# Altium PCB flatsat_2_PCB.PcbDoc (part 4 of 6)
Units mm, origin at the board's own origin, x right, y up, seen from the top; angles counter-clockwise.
Board outline 400 x 250 mm, 4 copper layers (Top Layer, FlatSat GND, FlatSat VCC, Bottom Layer), stack 2.102 mm thick; 196 components, 289 nets, 1724 pads, 1139 vias.
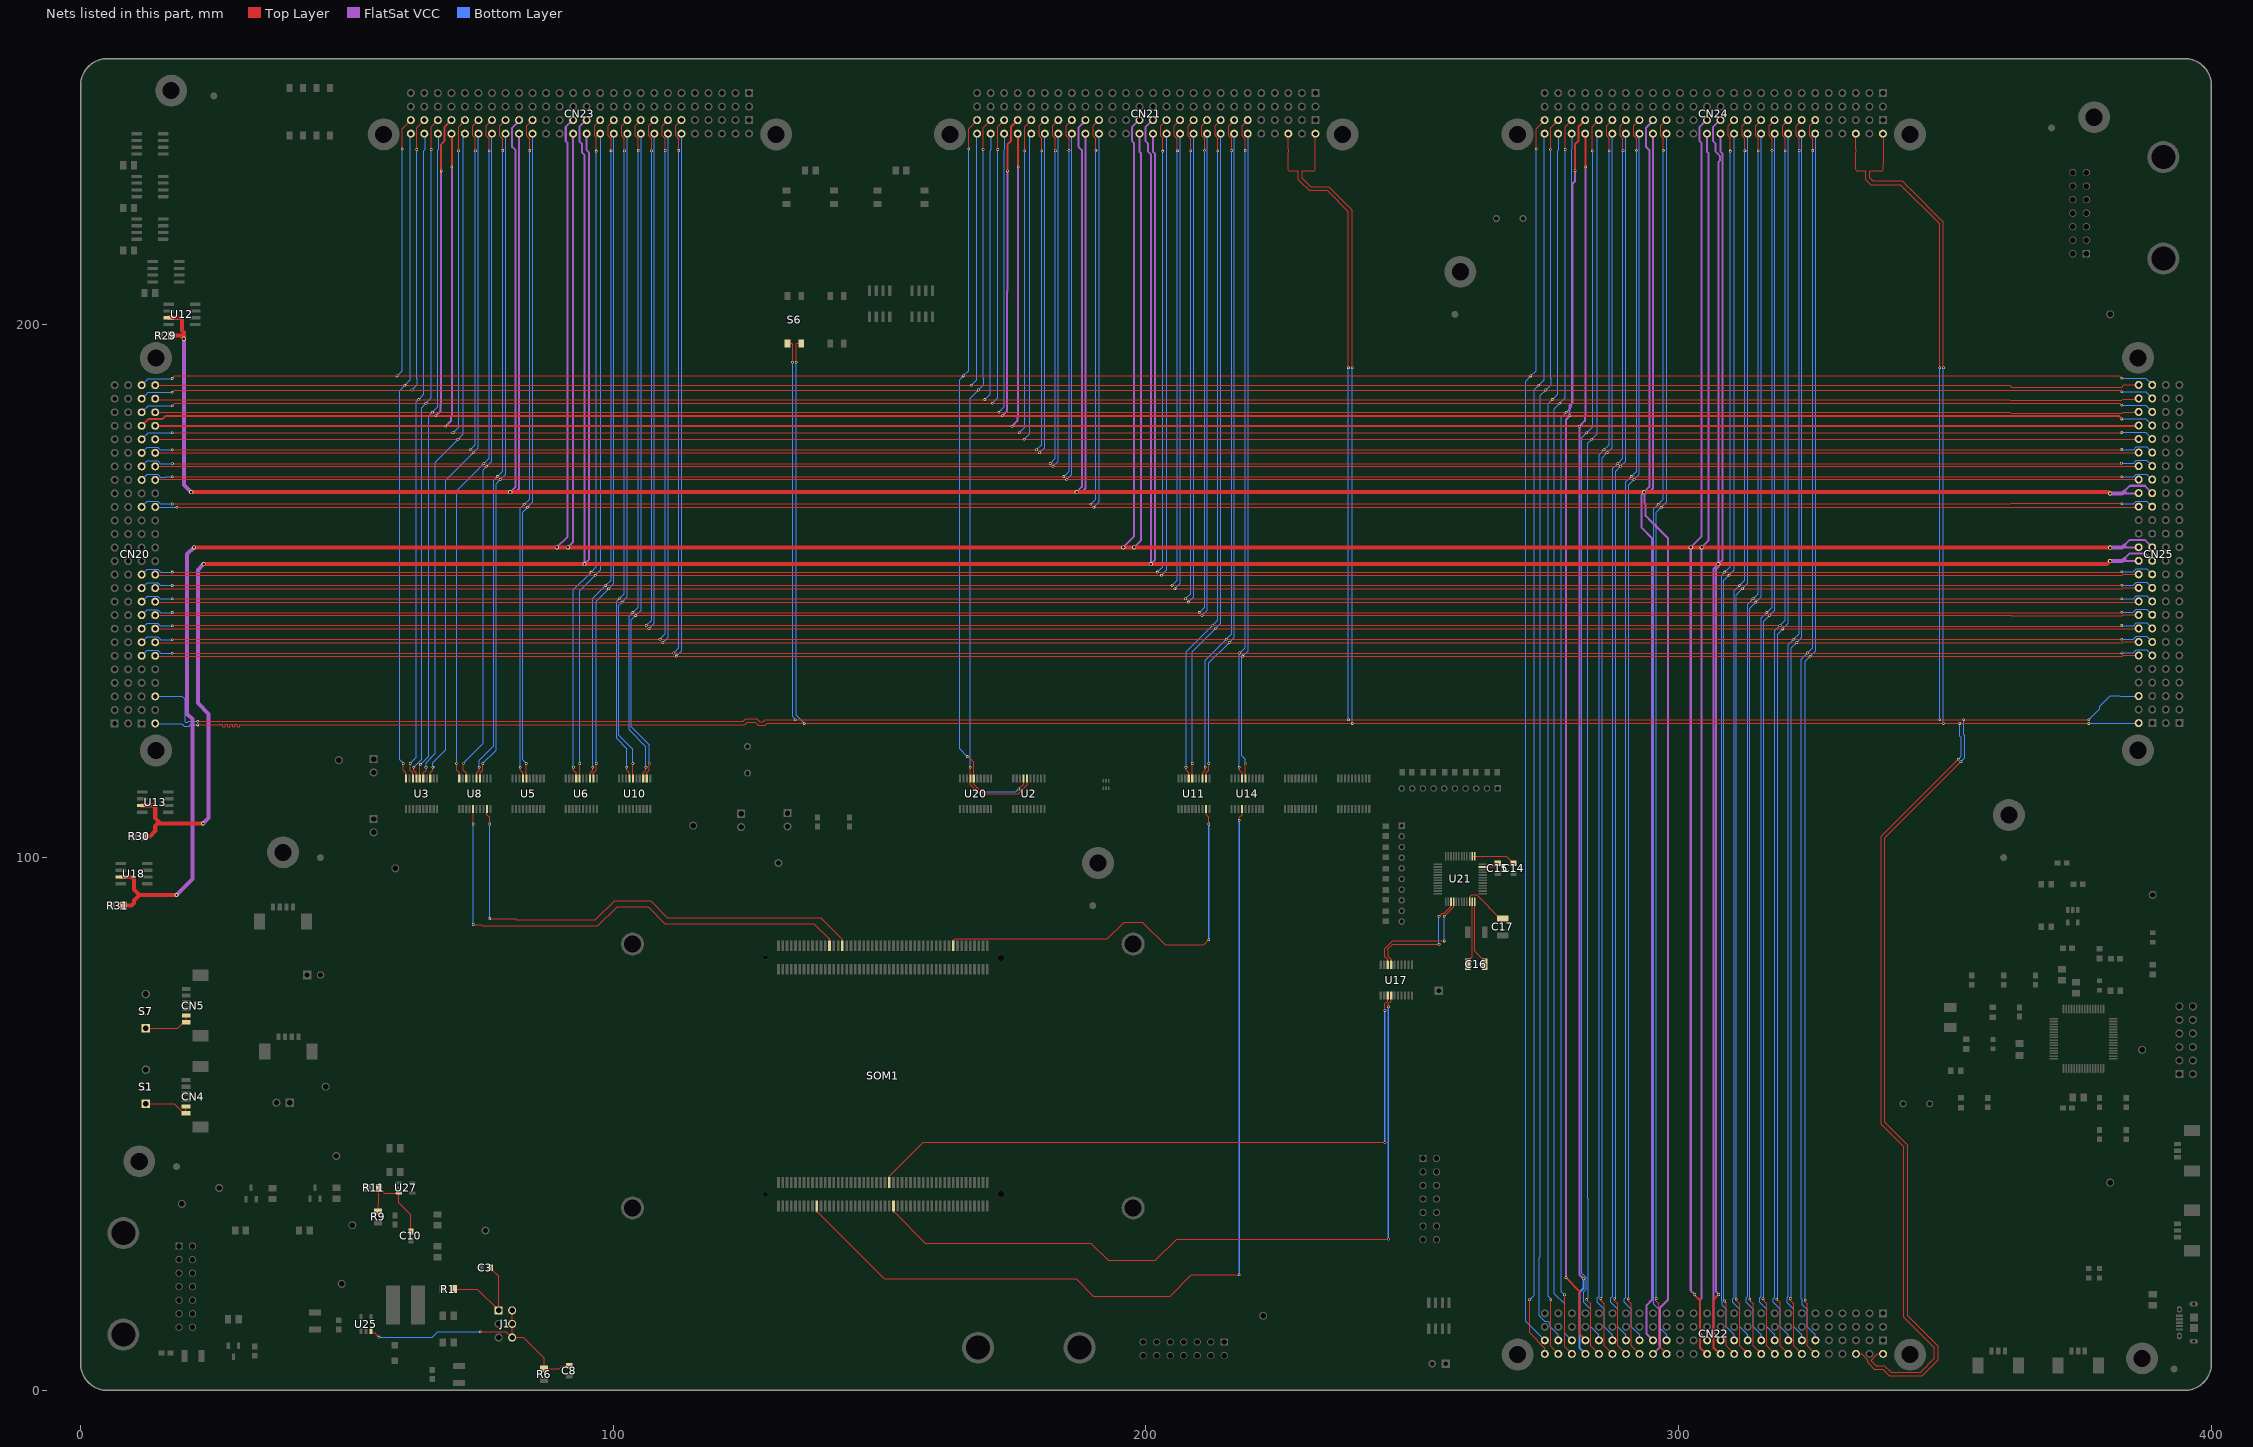
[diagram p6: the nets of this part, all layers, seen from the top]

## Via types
v1: diameter 0.508, hole 0.3, Top Layer to Bottom Layer, tented both sides, 1073 vias
v2: diameter 0.762, hole 0.45, Top Layer to Bottom Layer, tented both sides, 66 vias

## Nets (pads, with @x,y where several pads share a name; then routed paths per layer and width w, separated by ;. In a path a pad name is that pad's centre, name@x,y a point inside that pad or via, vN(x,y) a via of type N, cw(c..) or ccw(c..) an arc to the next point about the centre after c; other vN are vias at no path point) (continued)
H2-11: CN20.63 CN21.63 CN22.63 CN23.63 CN24.63 CN25.63 U14.17 | length 836.7
  Top Layer w0.203: v1(17.173,138.375) 17.215,138.418 v1(111.305,138.418) v1(217.625,138.418) v1(324.165,138.418) 324.211,138.371 382.95,138.371 382.955,138.376 383.163,138.376 v1(383.221,138.435) ; v1@112.306,232.749 112.306,234.909 111.73,235.485 111.73,237.415 CN23.63@112.78,238.465 ; v1(217.518,116.994) 217.518,116.421 218.025,115.913 U14.17@218.025,114.87 ; v1@218.626,232.749 218.626,234.909 218.05,235.485 218.05,237.415 CN21.63@219.1,238.465 ; v1@325.166,232.749 325.166,234.909 324.59,235.485 324.59,237.415 CN24.63@325.64,238.465
  Bottom Layer w0.203: CN20.63@11.455,137.9 12.505,138.95 14.435,138.95 15.011,138.374 17.171,138.374 v1(17.173,138.375) ; v1(111.305,138.418) 112.305,139.418 v1(112.305,232.747) v1@112.306,232.749 ; v1(217.518,116.994) 217.518,138.228 217.625,138.335 v1(217.625,138.418) 218.625,139.418 v1(218.625,232.747) ; v1(325.165,232.747) 325.165,139.418 v1(324.165,138.418) 323,137.253 323,17.193 323.243,16.95 323.243,16.111 324.158,15.196 324.158,11.978 325.668,10.467 CN22.63@325.668,9.388 ; v1(383.221,138.435) 385.36,138.435 385.93,139.005 387.86,139.005 CN25.63@388.91,137.955
H2-12: CN20.64 CN21.64 CN22.64 CN23.64 CN24.64 CN25.64 U14.16 | length 823.3
  Top Layer w0.203: CN20.64@14,137.9 14.058,137.842 v1(111.838,137.842) v1(218.158,137.842) 218.16,137.84 324.696,137.84 v1(324.698,137.838) ; U14.16@218.675,114.87 v1(218.675,117.679) ; v1(323.777,16.895) 323.718,16.837 323.718,16.669 323.708,16.658 324.158,16.208 324.158,8.354 CN22.64@325.668,6.843 ; v1@324.698,137.842 383.359,137.842 383.479,137.962 386.358,137.962 CN25.64@386.365,137.955
  Bottom Layer w0.203: v1(111.838,137.842) 112.838,138.842 CN23.64@112.838,235.862 ; v1(218.675,117.679) 218.675,118.446 218,119.121 218,137.601 218.158,137.759 v1(218.158,137.842) 219.158,138.842 CN21.64@219.158,235.862 ; v1(323.777,16.895) 323.722,16.95 323.722,136.865 324.694,137.838 v1(324.698,137.838) ; v1@324.698,137.842 325.698,138.842 CN24.64@325.698,235.862
H2-13: CN20.65 CN21.65 CN22.65 CN23.65 CN24.65 CN25.65 U11.13 | length 835.7
  Top Layer w0.203: v1(17.166,140.925) 17.225,140.983 17.421,140.983 17.438,141 v1(108.755,141) v1(215.075,141) v1(321.615,141) 383.178,141 v1(383.199,140.979) v1@383.179,140.96 ; v1(109.755,232.754) 109.755,234.92 109.19,235.485 109.19,237.41 CN23.65@110.24,238.46 ; U11.13@210.625,114.87 210.625,115.913 211.132,116.421 v1(211.132,116.994) ; v1(216.075,232.754) 216.075,234.92 215.51,235.485 215.51,237.41 CN21.65@216.56,238.46 ; v1(322.615,232.754) 322.615,234.92 322.05,235.485 322.05,237.41 CN24.65@323.1,238.46
  Bottom Layer w0.203: CN20.65@11.46,140.44 12.51,141.49 14.435,141.49 15,140.925 v1(17.166,140.925) ; v1(108.755,141) 109.755,142 v1(109.755,232.754) ; v1(211.132,116.994) 211.132,137.057 v1(215.075,141) 216.075,142 v1(216.075,232.754) ; v1(322.615,232.754) 322.615,142 v1(321.615,141) 320.615,140 320.615,36 320.615,17.648 320.381,17.414 320.381,16.433 321.618,15.196 321.618,11.978 323.128,10.467 CN22.65@323.128,9.383 ; v1(383.199,140.979) 385.365,140.979 385.93,141.545 387.855,141.545 CN25.65@388.905,140.495
H2-14: CN20.66 CN21.66 CN22.66 CN23.66 CN24.66 CN25.66 U11.12 | length 822.4
  Top Layer w0.203: CN20.66@14,140.44 14.049,140.391 v1(109.289,140.391) v1(215.609,140.391) v1(322.149,140.391) 383.365,140.391 383.489,140.515 386.345,140.515 CN25.66@386.365,140.495 ; U11.12@211.275,114.87 211.275,115.913 211.782,116.421 v1(211.782,117.679) ; v1(320.957,17.235) 320.957,16.869 321.618,16.208 321.618,8.354 CN22.66@323.128,6.843
  Bottom Layer w0.203: v1(109.289,140.391) 110.289,141.391 CN23.66@110.289,235.871 ; v1(211.782,117.679) 211.782,136.564 v1(215.609,140.391) 216.609,141.391 CN21.66@216.609,235.871 ; v1(320.957,17.235) 320.957,17.312 321.151,17.507 321.151,139.393 v1(322.149,140.391) 323.149,141.391 CN24.66@323.149,235.871
H2-15: CN20.67 CN21.67 CN22.67 CN23.67 CN24.67 CN25.67 U11.17 | length 833.5
  Top Layer w0.203: v1(17.185,143.514) 17.244,143.572 17.442,143.572 17.457,143.587 v1(106.166,143.587) v1(212.486,143.587) v1(319.026,143.587) 319.109,143.587 319.215,143.481 382.908,143.481 382.938,143.51 383.122,143.51 v1(383.18,143.569) ; v1(107.166,232.735) 107.166,234.969 106.65,235.485 106.65,237.41 CN23.67@107.7,238.46 ; v1(207.518,116.994) 207.518,116.421 208.025,115.913 U11.17@208.025,114.87 ; v1(213.486,232.735) 213.486,234.969 212.97,235.485 212.97,237.41 CN21.67@214.02,238.46 ; v1(320.026,232.735) 320.026,234.969 319.51,235.485 319.51,237.41 CN24.67@320.56,238.46
  Bottom Layer w0.203: CN20.67@11.46,142.98 12.51,144.03 14.435,144.03 14.951,143.514 v1(17.185,143.514) ; v1(106.166,143.587) 107.166,144.587 v1(107.166,232.735) ; v1(207.518,116.994) 207.518,138.618 v1(212.486,143.587) 213.486,144.587 v1(213.486,232.735) ; v1(320.026,232.735) 320.026,144.587 v1(319.026,143.587) 318.038,142.598 318.038,17.481 317.767,17.21 317.767,16.508 319.078,15.196 319.078,11.978 320.588,10.467 CN22.67@320.588,9.383 ; v1(383.18,143.569) 385.414,143.569 385.93,144.085 387.855,144.085 CN25.67@388.905,143.035
H2-16: CN20.68 CN21.68 CN22.68 CN23.68 CN24.68 CN25.68 U11.16 | length 819.9
  Top Layer w0.203: CN20.68@14,142.98 v1(106.7,142.98) v1(213.02,142.98) 213.036,142.964 319.544,142.964 v1(319.56,142.947) ; U11.16@208.675,114.87 v1(208.675,117.679) ; v1(318.437,17.126) 319.078,16.485 319.078,8.354 CN22.68@320.588,6.843 ; v1@319.56,142.98 386.31,142.98 CN25.68@386.365,143.035
  Bottom Layer w0.203: v1(106.7,142.98) 107.7,143.98 CN23.68@107.7,235.92 ; v1(208.675,117.679) 208.675,138.635 v1(213.02,142.98) 214.02,143.98 CN21.68@214.02,235.92 ; v1(318.437,17.126) 318.437,17.255 318.56,17.378 318.56,36 318.56,141.98 319.527,142.947 v1(319.56,142.947) ; v1@319.56,142.98 320.56,143.98 CN24.68@320.56,235.92
H2-17: CN20.69 CN21.69 CN22.69 CN23.69 CN24.69 CN25.69 U10.13 | length 830.6
  Top Layer w0.203: v1(17.179,146.014) v1(103.666,146.014) v1(209.986,146.014) v1(316.526,146.014) 383.131,146.014 v1(383.186,146.069) ; v1(104.666,232.741) 104.666,234.929 104.11,235.485 104.11,237.435 CN23.69@105.135,238.46 ; U10.13@105.625,114.87 105.625,115.913 106.132,116.421 v1(106.132,116.994) ; v1(210.986,232.741) 210.986,234.929 210.43,235.485 210.43,237.435 CN21.69@211.455,238.46 ; v1(317.526,232.741) 317.526,234.929 316.97,235.485 316.97,237.435 CN24.69@317.995,238.46
  Bottom Layer w0.203: CN20.69@11.46,145.545 12.485,146.57 14.435,146.57 14.991,146.014 v1(17.179,146.014) ; v1(104.666,232.741) 104.666,147.014 v1(103.666,146.014) 103,145.348 103,124 106.132,120.868 v1(106.132,116.994) ; v1(209.986,146.014) 210.986,147.014 v1(210.986,232.741) ; v1(317.526,232.741) 317.526,147.014 v1(316.526,146.014) 315.526,145.014 315.526,36 315.526,17.639 315.227,17.339 315.227,16.508 316.538,15.196 316.538,11.978 318.048,10.467 CN22.69@318.048,9.383 ; v1(383.186,146.069) 385.374,146.069 385.93,146.625 387.88,146.625 CN25.69@388.905,145.6
H2-18: CN20.70 CN21.70 CN22.70 CN23.70 CN24.70 CN25.70 U10.12 | length 817.9
  Top Layer w0.203: CN20.70@14,145.52 14.04,145.48 v1(104.2,145.48) v1(210.52,145.48) v1(317.06,145.48) 362.403,145.48 362.456,145.428 383.3,145.428 383.473,145.602 386.339,145.602 CN25.70@386.365,145.575 ; CN23.70@105.16,235.92 CN23.70@105.2,235.88 ; U10.12@106.275,114.87 106.275,115.913 106.782,116.421 v1(106.782,117.679) ; CN21.70@211.48,235.92 CN21.70@211.52,235.88 ; v1(315.834,17.192) 315.877,17.149 315.877,16.869 316.538,16.208 316.538,8.354 CN22.70@318.048,6.843 ; CN24.70@318.02,235.92 CN24.70@318.06,235.88
  Bottom Layer w0.203: CN23.70@105.16,235.92 105.2,235.88 105.2,146.48 v1(104.2,145.48) 103.381,144.662 103.381,124.619 106.782,121.218 v1(106.782,117.679) ; v1(210.52,145.48) 211.52,146.48 211.52,235.88 CN21.70@211.48,235.92 ; v1(315.834,17.192) 315.893,17.251 315.893,17.466 315.972,17.546 315.972,144.393 v1(317.06,145.48) 318.06,146.48 318.06,235.88 CN24.70@318.02,235.92
H2-19: CN20.71 CN21.71 CN22.71 CN23.71 CN24.71 CN25.71 U10.17 | length 827.4
  Top Layer w0.203: v1(17.183,148.585) 17.188,148.58 18.699,148.58 18.704,148.585 v1(101.095,148.585) v1(207.415,148.585) v1(313.955,148.585) 383.135,148.585 v1(383.182,148.632) ; v1@102.1,232.732 v1(102.095,232.737) 102.095,234.96 101.57,235.485 101.57,237.41 CN23.71@102.62,238.46 ; v1(102.518,116.994) 102.518,116.421 103.025,115.913 U10.17@103.025,114.87 ; v1@208.42,232.732 v1(208.415,232.737) 208.415,234.96 207.89,235.485 207.89,237.41 CN21.71@208.94,238.46 ; v1@314.96,232.732 v1(314.955,232.737) 314.955,234.96 314.43,235.485 314.43,237.41 CN24.71@315.48,238.46
  Bottom Layer w0.203: CN20.71@11.46,148.06 12.51,149.11 14.435,149.11 14.96,148.585 v1(17.183,148.585) ; v1(102.095,232.737) 102.095,149.585 v1(101.095,148.585) 100.605,148.094 100.605,122.395 102.518,120.482 v1(102.518,116.994) ; v1(207.415,148.585) 208.415,149.585 v1(208.415,232.737) ; v1(314.955,232.737) 314.955,149.585 v1(313.955,148.585) 312.98,147.609 312.98,17.656 312.687,17.363 312.687,16.508 313.998,15.196 313.998,11.978 315.508,10.467 CN22.71@315.508,9.383 ; v1(383.182,148.632) 383.19,148.64 385.405,148.64 385.93,149.165 387.855,149.165 CN25.71@388.905,148.115
H2-20: CN20.72 CN21.72 CN22.72 CN23.72 CN24.72 CN25.72 U10.16 | length 814.5
  Top Layer w0.203: CN20.72@14,148.06 14.078,147.982 v1(101.629,147.982) v1(207.949,147.982) v1(314.489,147.982) 386.232,147.982 CN25.72@386.365,148.115 ; U10.16@103.675,114.87 v1(103.675,117.679) ; v1(313.342,17.11) 313.337,17.106 313.337,16.869 313.998,16.208 313.998,8.354 CN22.72@315.508,6.843
  Bottom Layer w0.203: CN23.72@102.629,235.911 102.629,148.982 v1(101.629,147.982) 101,147.353 101,123 103.675,120.325 v1(103.675,117.679) ; v1(207.949,147.982) 208.949,148.982 CN21.72@208.949,235.911 ; v1(313.342,17.11) 313.361,17.129 313.361,146.854 v1(314.489,147.982) 315.489,148.982 CN24.72@315.489,235.911
H2-21: CN20.73 CN21.73 CN22.73 CN23.73 CN24.73 CN25.73 U6.13 | length 825
  Top Layer w0.203: v1(17.187,151.105) v1(98.575,151.105) v1(204.895,151.105) v1(311.435,151.105) 383.123,151.105 v1(383.178,151.16) ; U6.13@95.625,114.87 95.625,115.913 96.132,116.421 v1(96.132,116.994) ; v1(99.575,232.733) 99.575,234.94 99.03,235.485 99.03,237.41 CN23.73@100.08,238.46 ; v1(205.895,232.733) 205.895,234.94 205.35,235.485 205.35,237.41 CN21.73@206.4,238.46 ; v1(312.435,232.733) 312.435,234.94 311.89,235.485 311.89,237.41 CN24.73@312.94,238.46
  Bottom Layer w0.203: CN20.73@11.46,150.6 12.51,151.65 14.435,151.65 14.98,151.105 v1(17.187,151.105) ; v1(96.132,116.994) 96.132,148.663 v1(98.575,151.105) 99.575,152.105 v1(99.575,232.733) ; v1(204.895,151.105) 205.895,152.105 v1(205.895,232.733) ; v1(312.435,232.733) 312.435,152.105 v1(311.435,151.105) 310.452,150.123 310.452,17.515 310.147,17.21 310.147,16.508 311.458,15.196 311.458,11.978 312.968,10.467 CN22.73@312.968,9.383 ; v1(383.178,151.16) 385.386,151.16 385.93,151.705 387.855,151.705 CN25.73@388.905,150.655
H2-22: CN20.74 CN21.74 CN22.74 CN23.74 CN24.74 CN25.74 U6.12 | length 811.8
  Top Layer w0.203: CN20.74@14,150.6 14.123,150.477 v1(99.108,150.477) v1(205.428,150.477) v1(311.968,150.477) 383.249,150.477 383.479,150.706 386.314,150.706 CN25.74@386.365,150.655 ; U6.12@96.275,114.87 96.275,115.913 96.782,116.421 v1(96.782,117.679) ; v1@310.797,17.106 310.797,16.869 311.458,16.208 311.458,8.354 CN22.74@312.968,6.843
  Bottom Layer w0.203: v1(96.782,117.679) 96.782,148.151 v1(99.108,150.477) 100.108,151.477 CN23.74@100.108,235.892 ; v1(205.428,150.477) 206.428,151.477 CN21.74@206.428,235.892 ; v1(310.798,17.106) 310.833,17.141 310.833,149.342 v1(311.968,150.477) 312.968,151.477 CN24.74@312.968,235.892
H2-23: CN20.75 CN21.75 CN22.75 CN23.75 CN24.75 CN25.75 U6.17 | length 822
  Top Layer w0.203: v1(17.183,153.612) v1(95.818,153.612) v1(202.138,153.612) v1(308.678,153.612) 383.128,153.612 v1(383.183,153.667) ; v1(92.518,116.994) 92.518,116.421 93.025,115.913 U6.17@93.025,114.87 ; v1(96.818,232.653) 96.818,235.157 96.49,235.485 96.49,237.41 CN23.75@97.54,238.46 ; v1(203.138,232.653) 203.138,235.157 202.81,235.485 202.81,237.41 CN21.75@203.86,238.46 ; v1(309.678,232.653) 309.678,235.157 309.35,235.485 309.35,237.41 CN24.75@310.4,238.46
  Bottom Layer w0.203: CN20.75@11.46,153.14 12.51,154.19 14.435,154.19 15.013,153.612 v1(17.183,153.612) ; v1(92.518,116.994) 92.518,150.312 v1(95.818,153.612) 96.818,154.612 v1(96.818,232.653) ; v1(202.138,153.612) 203.138,154.612 v1(203.138,232.653) ; v1(309.678,232.653) 309.678,154.612 308.126,153.061 308.126,16.859 308.136,16.849 308.136,15.978 308.918,15.196 308.918,11.978 310.428,10.467 CN22.75@310.428,9.383 ; v1(383.183,153.667) 385.352,153.667 385.93,154.245 387.855,154.245 CN25.75@388.905,153.195
H2-24: CN20.76 CN21.76 CN22.76 CN23.76 CN24.76 CN25.76 U6.16 | length 809.3
  Top Layer w0.203: CN20.76@14,153.14 14.122,153.018 v1(96.601,153.018) v1(202.921,153.018) v1(309.461,153.018) 383.288,153.018 383.502,153.231 386.329,153.231 CN25.76@386.365,153.195 ; U6.16@93.675,114.87 v1(93.675,117.679) ; v1(308.67,16.772) 308.67,16.69 308.918,16.442 308.918,8.354 CN22.76@310.428,6.843
  Bottom Layer w0.203: v1(93.675,117.679) 93.675,150.092 v1(96.601,153.018) 97.601,154.018 97.601,235.859 CN23.76@97.54,235.92 ; v1(202.921,153.018) 203.921,154.018 203.921,235.859 CN21.76@203.86,235.92 ; v1(308.67,16.772) 308.67,16.855 308.508,17.017 308.508,152.064 310.461,154.018 310.461,235.859 CN24.76@310.4,235.92
H2-25: CN21.77 CN21.78 CN22.77 CN22.78 CN23.77 CN23.78 CN24.77 CN24.78 CN25.77 CN25.78 R30.2 U13.7 | length 1232.5
  Top Layer w0.381: v1(307.54,18) 306.54,17 306.54,8 CN22.78@307.697,6.843
  Top Layer w0.762: U13.7@11.53,109.788 13.554,109.788 14,109.342 14,107.423 15,106.423 ; R30.2@12.016,104 13,104 14,105 14,105.977 14.446,106.423 15,106.423 ; v2(23,106.423) 15,106.423 ; v2(23.099,155.099) v2(94.582,155.099) v2(200.902,155.099) v2(307.442,155.099) 380.441,155.099 v2(381,155.658)
  FlatSat VCC w0.381: v2@94.544,155.099 95.461,156.016 95.461,232.373 95,232.834 CN23.78@95,235.92 ; v2(94.582,155.099) 94.544,155.137 94.544,231.956 94.074,232.426 94.074,234.06 93.609,234.526 93.609,237.19 CN23.77@94.879,238.46 ; v2(200.902,155.099) v2@200.949,155.146 ; CN21.77@201.199,238.46 199.929,237.19 199.929,234.526 200.394,234.06 200.394,232.546 200.949,231.991 v2@200.949,155.146 ; CN21.78@201.32,235.92 201.32,232.54 201.733,232.127 201.733,155.929 v2@200.949,155.146 ; v1(307.54,18) 307.54,18.034 307,18.574 307,154.087 307.442,154.529 v2(307.442,155.099) ; CN24.77@307.739,238.46 306.469,237.19 306.469,234.526 306.934,234.06 306.934,232.546 307.786,231.694 307.786,230.932 307.498,230.644 v2@307.498,155.155 ; CN24.78@307.86,235.92 307.86,232.54 308.273,232.127 308.273,155.929 v2@307.498,155.155 ; CN22.77@307.888,9.383 306.54,10.732 306.54,154.197 v2(307.442,155.099) ; 383.248,155.658 CN25.78@386.288,155.658 ; 383.671,156.081 384.71,157.12 387.521,157.12 CN25.77@388.905,155.735 ; v2(307.442,155.099) v2@307.498,155.155
  FlatSat VCC w0.762: v2(23,106.423) 24,107.423 24,127 22,129 22,154 v2(23.099,155.099) ; v2(381,155.658) 383.248,155.658 383.671,156.081
H2-27: CN21.79 CN21.80 CN22.79 CN22.80 CN23.79 CN23.80 CN24.79 CN24.80 CN25.79 CN25.80 R31.2 U18.7 | length 1239
  Top Layer w0.381: v1(303,18) 303,17.874 304,16.874 304,8 305.157,6.843 CN22.80@305.348,6.843
  Top Layer w0.762: U18.7@7.53,96.365 9.554,96.365 10,95.919 10,94 11,93 ; R31.2@8.016,91 9.554,91 10,91.446 10,92 11,93 ; v2(18,93) 11,93 ; v2(21.268,158.268) v2(89.408,158.268) v2(91.46,158.268) v2(195.728,158.268) v2(197.78,158.268) v2(302.268,158.268) v2(304.32,158.268) 380.929,158.268 v2(381,158.198)
  FlatSat VCC w0.381: v2(89.408,158.268) 91.408,160.268 91.408,234.187 91.069,234.526 91.069,237.19 92.339,238.46 CN23.79@92.46,238.46 ; v2(91.46,158.268) 92.46,159.268 CN23.80@92.46,235.92 ; v2(195.728,158.268) 197.728,160.268 197.728,234.187 197.389,234.526 197.389,237.19 198.659,238.46 CN21.79@198.78,238.46 ; v2(197.78,158.268) 199.088,159.576 199.088,232.232 198.78,232.54 CN21.80@198.78,235.92 ; v1(303,18) 302.268,18.732 v2(302.268,158.268) 304.268,160.268 304.268,234.187 303.929,234.526 303.929,237.19 305.199,238.46 CN24.79@305.32,238.46 ; CN24.80@305.32,235.92 305.32,232.54 305.628,232.232 305.628,159.576 v2(304.32,158.268) 304.32,17.32 304,17 304,10.732 CN22.79@305.348,9.383 ; 383.248,158.198 CN25.80@386.288,158.198 ; 383.671,158.621 384.71,159.66 387.521,159.66 CN25.79@388.905,158.275
  FlatSat VCC w0.762: v2(18,93) 21,96 21,126 20,127 20,157 v2(21.268,158.268) ; v2(381,158.198) 383.248,158.198 383.671,158.621
H2-33: CN20.85 CN21.85 CN22.85 CN23.85 CN24.85 CN25.85 U5.17 | length 808.7
  Top Layer w0.203: v1(17.179,166.398) 362.236,166.398 362.409,166.57 382.986,166.57 383.104,166.452 v1(383.186,166.452) ; v1(82.518,116.994) 82.518,116.421 83.025,115.913 U5.17@83.025,114.87 ; v1(84.282,232.741) 84.282,234.993 83.79,235.485 83.79,237.41 CN23.85@84.84,238.46 ; v1(190.602,232.741) 190.602,234.993 190.11,235.485 190.11,237.41 CN21.85@191.16,238.46 ; v1(297.142,232.741) 297.142,234.993 296.65,235.485 296.65,237.41 CN24.85@297.7,238.46
  Bottom Layer w0.203: CN20.85@11.46,165.84 12.51,166.89 14.435,166.89 14.927,166.398 v1(17.179,166.398) ; v1(82.518,116.994) 82.518,165.559 v1(83.282,166.324) 84.282,167.324 v1(84.282,232.741) ; v1(189.602,166.324) 190.602,167.324 v1(190.602,232.741) ; v1(297.142,232.741) 297.142,167.324 v1(296.142,166.324) 295.283,165.465 295.283,16.131 296.218,15.196 296.218,11.978 297.728,10.467 CN22.85@297.728,9.383 ; v1(383.186,166.452) 385.438,166.452 385.93,166.945 387.855,166.945 CN25.85@388.905,165.895
H2-34: CN20.86 CN21.86 CN22.86 CN23.86 CN24.86 CN25.86 U5.16 | length 796.1
  Top Layer w0.203: v1(18.039,165.791) v1(83.901,165.791) v1(190.221,165.791) v1(296.761,165.791) 386.261,165.791 CN25.86@386.365,165.895 ; U5.16@83.675,114.87 v1(83.675,117.679) ; v1(295.817,17.235) 295.817,17.153 295.557,16.893 295.557,16.869 296.218,16.208 296.218,8.354 CN22.86@297.728,6.843
  Bottom Layer w0.203: CN20.86@14,165.84 14.025,165.815 18.015,165.815 v1(18.039,165.791) ; v1(83.675,117.679) 83,118.354 83,164.889 v1(83.901,165.791) 84.901,166.791 84.901,235.859 CN23.86@84.84,235.92 ; v1(190.221,165.791) 191.221,166.791 191.221,235.859 CN21.86@191.16,235.92 ; v1(295.817,17.235) 295.806,17.246 295.806,164.835 v1(296.761,165.791) 297.761,166.791 297.761,235.859 CN24.86@297.7,235.92
H2-35: CN21.87 CN21.88 CN22.87 CN22.88 CN23.87 CN23.88 CN24.87 CN24.88 CN25.87 CN25.88 R29.2 U12.7 | length 1155.7
  Top Layer w0.762: U12.7@16.53,201.365 18.554,201.365 19,200.919 19,199 19.383,198.617 v2(19.383,197.419) 18.802,198 R29.2@17.016,198 ; v2(20.755,168.627) v2(80.652,168.627) v2(186.972,168.627) v2(293.512,168.627) 380.73,168.627 v2(381,168.358)
  FlatSat VCC w0.381: CN23.88@82.3,235.92 82.3,169.3 81.627,168.627 v2(80.652,168.627) 81.652,169.627 81.652,232.814 81,233.466 81,237 82.3,238.3 CN23.87@82.3,238.46 ; CN21.88@188.62,235.92 188.62,169.3 187.947,168.627 v2(186.972,168.627) 187.972,169.627 187.972,232.814 187.32,233.466 187.32,237 188.62,238.3 CN21.87@188.62,238.46 ; CN24.88@295.16,235.92 295.16,169.3 294.487,168.627 v2(293.512,168.627) ; CN24.87@295.16,238.46 295.16,238.3 293.86,237 293.86,233.466 294.512,232.814 294.512,169.627 v2(293.512,168.627) ; CN22.88@295.188,6.843 296.46,8.115 296.46,15.46 298,17 298,160 295,163 293.811,164.189 293.811,166.398 293.559,166.649 293.559,168.581 v2(293.512,168.627) ; CN22.87@295.188,9.383 294,10.572 294,16 295,17 295,160 293,162 293,168.012 293.512,168.524 v2(293.512,168.627) ; 383.248,168.358 386.288,168.358 CN25.88@386.365,168.435 ; 383.671,168.781 384.71,169.82 387.521,169.82 CN25.87@388.905,168.435
  FlatSat VCC w0.762: v2(19.383,197.419) 19.383,170 v2(20.755,168.627) ; v2(381,168.358) 383.248,168.358 383.671,168.781
H2-37: CN20.89 CN21.89 CN22.89 CN23.89 CN24.89 CN25.89 U8.15 | length 804.9
  Top Layer w0.203: v1(17.179,171.536) 17.207,171.536 17.237,171.505 17.409,171.505 17.45,171.547 v1(78.233,171.547) v1(184.553,171.547) v1(291.093,171.547) 383.05,171.547 383.061,171.536 v1(383.186,171.536) ; U8.15@74.325,114.87 74.325,115.913 74.832,116.421 v1(74.832,116.994) ; v1(79.233,232.741) 79.233,234.962 78.71,235.485 78.71,237.41 CN23.89@79.76,238.46 ; v1(185.553,232.741) 185.553,234.962 185.03,235.485 185.03,237.41 CN21.89@186.08,238.46 ; v1(292.093,232.741) 292.093,234.962 291.57,235.485 291.57,237.41 CN24.89@292.62,238.46
  Bottom Layer w0.203: CN20.89@11.46,170.92 12.51,171.97 14.435,171.97 14.958,171.447 15.983,171.447 16.072,171.536 v1(17.179,171.536) ; v1(74.832,116.994) 74.832,118.297 77.523,120.987 77.523,170.837 v1(78.233,171.547) 79.233,172.547 v1(79.233,232.741) ; v1(184.553,171.547) 185.553,172.547 v1(185.553,232.741) ; v1(292.093,232.741) 292.093,172.547 v1(291.093,171.547) 290.099,170.553 290.099,17.482 289.827,17.21 289.827,16.508 291.138,15.196 291.138,11.978 292.648,10.467 CN22.89@292.648,9.383 ; v1(383.186,171.536) 383.22,171.502 385.407,171.502 385.93,172.025 387.855,172.025 CN25.89@388.905,170.975
H2-38: CN20.90 CN21.90 CN22.90 CN23.90 CN24.90 CN25.90 U8.14 | length 791.7
  Top Layer w0.203: CN20.90@14,170.92 14.082,171.002 v1(78.767,171.002) v1(185.087,171.002) v1(291.627,171.002) 386.338,171.002 CN25.90@386.365,170.975 ; U8.14@74.975,114.87 74.975,115.913 75.482,116.421 v1(75.482,117.679) ; CN23.90@79.76,235.92 CN23.90@79.767,235.913 ; CN21.90@186.08,235.92 CN21.90@186.087,235.913 ; v1(290.546,17.19) 290.488,17.132 290.488,16.879 290.477,16.869 291.138,16.208 291.138,8.354 CN22.90@292.648,6.843 ; CN24.90@292.62,235.92 CN24.90@292.627,235.913
  Bottom Layer w0.203: v1(75.482,117.679) 78,120.196 78,170.236 v1(78.767,171.002) 79.767,172.002 CN23.90@79.767,235.913 ; v1(185.087,171.002) 186.087,172.002 CN21.90@186.087,235.913 ; v1(290.546,17.19) 290.546,17.273 290.627,17.353 290.627,36 290.627,170.002 v1(291.627,171.002) 292.627,172.002 CN24.90@292.627,235.913
H2-39: CN20.91 CN21.91 CN22.91 CN23.91 CN24.91 CN25.91 U8.20 | length 803.1
  Top Layer w0.203: v1(17.228,173.997) v1(75.683,173.997) v1(182.003,173.997) v1(288.542,173.997) 383.082,173.997 v1(383.137,174.052) ; v1(70.568,117.679) 70.568,116.421 71.075,115.913 U8.20@71.075,114.87 ; v1(76.683,232.692) 76.683,234.973 76.17,235.485 76.17,237.41 CN23.91@77.22,238.46 ; v1(183.003,232.692) 183.003,234.973 182.49,235.485 182.49,237.41 CN21.91@183.54,238.46 ; v1(289.542,232.692) 289.542,234.973 289.03,235.485 289.03,237.41 CN24.91@290.08,238.46
  Bottom Layer w0.203: CN20.91@11.46,173.46 12.51,174.51 14.435,174.51 14.947,173.997 v1(17.228,173.997) ; v1(70.568,117.679) 70.568,168.883 v1(75.683,173.997) 76.682,174.997 v1(76.683,232.692) ; v1(182.003,173.997) 183.002,174.997 v1(183.003,232.692) ; v1(289.542,232.692) 289.542,174.997 v1(288.542,173.997) 287.618,173.073 287.618,36 287.618,17.671 287.287,17.339 287.287,16.508 288.598,15.196 288.598,11.978 290.108,10.467 CN22.91@290.108,9.383 ; v1(383.137,174.052) 385.418,174.052 385.93,174.565 387.855,174.565 CN25.91@388.905,173.515
H2-40: CN20.92 CN21.92 CN22.92 CN23.92 CN24.92 CN25.92 U8.18 | length 789.6
  Top Layer w0.203: CN20.92@14,173.46 v1(76.22,173.46) v1(182.54,173.46) v1(289.08,173.46) 386.31,173.46 CN25.92@386.365,173.515 ; v1(71.868,117.679) 71.868,116.421 72.375,115.913 U8.18@72.375,114.87 ; v1(287.937,17.235) 287.937,16.869 288.598,16.208 288.598,8.354 CN22.92@290.108,6.843
  Bottom Layer w0.203: v1(71.868,117.679) 75.624,121.436 75.624,172.864 v1(76.22,173.46) 77.22,174.46 CN23.92@77.22,235.92 ; v1(182.54,173.46) 183.54,174.46 CN21.92@183.54,235.92 ; v1(287.937,17.235) 288.155,17.453 288.155,36 288.155,172.535 v1(289.08,173.46) 290.08,174.46 CN24.92@290.08,235.92
H2-41: CN20.93 CN21.93 CN22.93 CN23.93 CN24.93 CN25.93 | length 736.4
  Top Layer w0.203: v1(17.187,176.562) v1(73.118,176.562) v1(179.438,176.562) v1(285.978,176.562) 383.123,176.562 v1(383.178,176.617) ; v1(74.118,232.733) 74.118,234.998 73.63,235.485 73.63,237.41 CN23.93@74.68,238.46 ; v1(180.438,232.733) 180.438,234.998 179.95,235.485 179.95,237.41 CN21.93@181,238.46 ; v1(286.978,232.733) 286.978,234.998 286.49,235.485 286.49,237.41 CN24.93@287.54,238.46
  Bottom Layer w0.203: CN20.93@11.46,176 12.51,177.05 14.435,177.05 14.922,176.562 v1(17.187,176.562) ; v1(73.118,176.562) 74.118,177.562 v1(74.118,232.733) ; v1(179.438,176.562) 180.438,177.562 v1(180.438,232.733) ; v1(286.978,232.733) 286.978,177.562 v1(285.978,176.562) 285.053,175.638 285.053,36 285.053,17.646 284.747,17.339 284.747,16.508 286.058,15.196 286.058,11.978 287.568,10.467 CN22.93@287.568,9.383 ; v1(383.178,176.617) 385.443,176.617 385.93,177.105 387.855,177.105 CN25.93@388.905,176.055
H2-42: CN20.94 CN21.94 CN22.94 CN23.94 CN24.94 CN25.94 U3.13 | length 788.4
  Top Layer w0.203: CN20.94@14,176 v1(73.68,176) v1(180,176) v1(286.54,176) 386.31,176 CN25.94@386.365,176.055 ; U3.13@65.625,114.87 65.625,115.913 66.132,116.421 v1(66.132,116.994) ; v1(285.397,17.235) 285.397,16.869 286.058,16.208 286.058,8.354 CN22.94@287.568,6.843
  Bottom Layer w0.203: v1(66.132,116.994) 66.132,117.783 68.568,120.219 68.568,170.888 v1(73.68,176) 74.68,177 CN23.94@74.68,235.92 ; v1(180,176) 181,177 CN21.94@181,235.92 ; v1(285.397,17.235) 285.615,17.453 285.615,36 285.615,175.075 v1(286.54,176) 287.54,177 CN24.94@287.54,235.92
H2-43: CN20.95 CN21.95 CN22.95 CN23.95 CN24.95 CN25.95 | length 730
  Top Layer w0.203: v1(17.192,179.777) v1(69.903,179.777) v1(176.223,179.777) v1(282.763,179.777) 383.119,179.777 v1(383.174,179.832) ; v1(70.941,232.728) 70.941,237.261 CN23.95@72.14,238.46 ; v1(177.223,232.728) 177.223,237.223 CN21.95@178.46,238.46 ; v1(283.763,232.728) 283.763,237.223 CN24.95@285,238.46
  Bottom Layer w0.203: CN20.95@11.46,178.54 12.697,179.777 v1(17.192,179.777) ; v1(69.903,179.777) 70.941,180.815 v1(70.941,232.728) ; v1(176.223,179.777) 177.263,180.817 177.263,232.688 v1(177.223,232.728) ; v1(283.763,232.728) 283.821,232.67 283.821,232.499 283.863,232.457 283.863,180.877 v1(282.763,179.777) 281.838,178.852 281.838,36 281.838,22.007 282.666,21.179 282.666,19.001 282.157,18.492 282.157,16.557 283.518,15.196 283.518,11.978 285.028,10.467 CN22.95@285.028,9.383 ; v1(383.174,179.832) 387.668,179.832 CN25.95@388.905,178.595
H2-44: CN20.96 CN21.96 CN22.96 CN23.96 CN24.96 CN25.96 U3.15 | length 785.7
  Top Layer w0.203: CN20.96@14,178.54 v1(70.84,178.54) v1(177.16,178.54) v1(283.7,178.54) 386.31,178.54 CN25.96@386.365,178.595 ; U3.15@64.325,114.87 64.325,115.913 64.832,116.421 v1(64.832,116.994) ; v1(282.691,17.035) 283.518,16.208 283.518,8.354 CN22.96@285.028,6.843
  Bottom Layer w0.203: v1(64.832,116.994) 64.832,117.832 66.568,119.568 66.568,174.267 v1(70.84,178.54) 71.84,179.54 71.84,235.153 71.892,235.204 71.892,235.672 CN23.96@72.14,235.92 ; v1(177.16,178.54) 178.16,179.54 178.16,235.153 178.212,235.204 178.212,235.672 CN21.96@178.46,235.92 ; v1(282.691,17.035) 283.047,17.392 283.047,35.878 282.925,36 282.925,177.765 v1(283.7,178.54) 284.7,179.54 284.7,235.153 284.752,235.204 284.752,235.672 CN24.96@285,235.92
H2-45: CN20.97 CN21.97 CN22.97 CN23.97 CN24.97 CN25.97 | length 724.5
  Top Layer w0.203: v1@383.146,182.344 v1(383.174,182.372)
  Top Layer w0.381: CN20.97@11.46,181.08 12.724,182.344 15.344,182.344 15.94,182.94 v1(66.682,182.94) v1(173.002,182.94) v1(279.542,182.94) 382.574,182.94 383.146,182.368 v1@383.146,182.344 ; v1(67.679,228.921) 67.68,228.923 67.68,233.92 68.336,234.576 68.336,237.196 CN23.97@69.6,238.46 ; v1(173.999,228.921) 174,228.923 174,233.92 174.656,234.576 174.656,237.196 CN21.97@175.92,238.46 ; v1(278.857,21.143) 281.37,18.63 281.37,10.63 282.488,9.512 CN22.97@282.488,9.383 ; v1(280.539,228.921) 280.54,228.923 280.54,233.92 281.196,234.576 281.196,237.196 CN24.97@282.46,238.46
  FlatSat VCC w0.381: v1(66.682,182.94) 67.559,183.817 67.559,184.925 67.682,185.048 67.682,228.918 v1(67.679,228.921) ; v1(173.002,182.94) 173.879,183.817 173.879,206.292 173.999,206.412 v1(173.999,228.921) ; v1(278.857,21.143) 278.857,182.255 v1(279.542,182.94) 279.542,184.882 280.076,185.415 280.076,226.537 280.539,227 v1(280.539,228.921)
  Bottom Layer w0.203: v1(383.174,182.372) 387.668,182.372 CN25.97@388.905,181.135
H2-46: CN20.98 CN21.98 CN22.98 CN23.98 CN24.98 CN25.98 | length 714
  Top Layer w0.381: CN20.98@14,181.08 14.08,181 v1(68.53,181) v1(174.85,181) v1(281.39,181) 386.23,181 CN25.98@386.365,181.135 ; CN23.98@69.6,235.92 69.683,235.837 v1(69.683,229.682) ; CN21.98@175.92,235.92 176.003,235.837 v1(176.003,229.682) ; CN24.98@282.46,235.92 282.543,235.837 v1(282.543,229.682)
  FlatSat VCC w0.381: v1(68.53,181) 69.53,182 69.53,182.755 69.683,182.908 v1(69.683,229.682) ; v1(174.85,181) 175.85,182 175.85,182.755 176.003,182.908 v1(176.003,229.682) ; v1(282.133,20.958) 281.39,21.7 v1(281.39,181) 282.39,182 282.39,182.755 282.543,182.908 v1(282.543,229.682)
  Bottom Layer w0.381: v1(282.133,20.958) 282.133,19.133 281.37,18.37 281.37,7.962 CN22.98@282.488,6.843
H2-47: CN20.99 CN21.99 CN22.99 CN23.99 CN24.99 CN25.99 U3.17 | length 790.4
  Top Layer w0.203: v1(17.192,184.857) 17.658,185.323 v1(64.823,185.323) v1(171.143,185.323) v1(277.683,185.323) 382.762,185.323 383.146,184.939 383.146,184.884 v1(383.174,184.912) ; v1(62.518,116.994) 62.518,116.421 63.025,115.913 U3.17@63.025,114.87 ; v1(65.823,232.95) 65.823,237.223 CN23.99@67.06,238.46 ; v1(172.143,232.95) 172.143,237.223 CN21.99@173.38,238.46 ; v1(278.683,232.95) 278.683,237.223 CN24.99@279.92,238.46
  Bottom Layer w0.203: CN20.99@11.46,183.62 12.697,184.857 v1(17.192,184.857) ; v1(62.518,116.994) 64,118.477 64,184.5 v1(64.823,185.323) 65.823,186.323 v1(65.823,232.95) ; v1(171.143,185.323) 172.143,186.323 v1(172.143,232.95) ; v1(278.683,232.95) 278.683,186.323 v1(277.683,185.323) 276.683,184.323 276.683,36 276.683,18.171 278.584,16.27 278.584,10.747 CN22.99@279.948,9.383 ; v1(383.174,184.912) 387.668,184.912 CN25.99@388.905,183.675
H2-48: CN20.100 CN21.100 CN22.100 CN23.100 CN24.100 CN25.100 U3.16 | length 778.7
  Top Layer w0.203: CN20.100@14,183.62 v1(66.04,183.62) v1(172.36,183.62) v1(278.9,183.62) 362.182,183.62 362.392,183.41 383.273,183.41 383.483,183.62 386.31,183.62 CN25.100@386.365,183.675 ; U3.16@63.675,114.87 63.675,117.315 63.816,117.456 v1(63.816,117.538) ; v1(278.573,17.927) 278.573,8.218 CN22.100@279.948,6.843
  Bottom Layer w0.203: v1(63.816,117.538) 65.356,119.078 65.356,182.935 v1(66.04,183.62) 67.04,184.62 67.04,232.811 67.186,232.957 67.186,235.794 CN23.100@67.06,235.92 ; v1(172.36,183.62) 173.36,184.62 173.36,232.811 173.506,232.957 173.506,235.794 CN21.100@173.38,235.92 ; v1(278.573,17.927) 277.985,18.515 277.985,36 277.985,182.705 v1(278.9,183.62) 279.9,184.62 279.9,232.811 280.046,232.957 280.046,235.794 CN24.100@279.92,235.92
H2-49: CN20.101 CN21.101 CN22.101 CN23.101 CN24.101 CN25.101 U2.17 U20.17 | length 801.8
  Top Layer w0.203: v1(17.192,187.397) 17.23,187.397 17.622,187.789 v1(62.201,187.789) v1(168.521,187.789) v1(275.061,187.789) 382.762,187.789 383.126,187.424 383.146,187.424 v1(383.174,187.452) ; v1(63.091,232.956) 63.091,237.031 CN23.101@64.52,238.46 ; v1(167,117) 167.025,116.975 U20.17@167.025,114.87 167.025,113.685 168.084,112.626 168.084,112.398 v1(168.143,112.339) ; v1(169.411,232.956) 169.411,237.031 CN21.101@170.84,238.46 ; v1(176.14,112.898) 177.025,113.782 U2.17@177.025,114.87 ; v1(275.951,232.956) 275.951,237.031 CN24.101@277.38,238.46
  Bottom Layer w0.203: CN20.101@11.46,186.16 12.697,187.397 v1(17.192,187.397) ; v1(62.201,187.789) 63.201,188.789 63.201,189.89 63.091,190 v1(63.091,232.956) ; v1(167,117) 167,186.268 v1(168.521,187.789) 169.521,188.789 169.521,189.89 169.411,190 v1(169.411,232.956) ; v1(168.143,112.339) 175.582,112.339 v1(176.14,112.898) ; v1(275.951,232.956) 275.951,190 276.061,189.89 276.061,188.789 v1(275.061,187.789) 274.061,186.789 274.061,36 274.061,25.129 273.839,24.907 273.839,14.037 274.875,13 275.398,13 275.927,12.472 275.927,11.949 277.408,10.467 CN22.101@277.408,9.383 ; v1(383.174,187.452) 387.668,187.452 CN25.101@388.905,186.215
H2-50: CN20.102 CN21.102 CN22.102 CN23.102 CN24.102 CN25.102 U3.18 | length 776.3
  Top Layer w0.203: CN20.102@14,186.16 14.157,186.003 v1(63.427,186.003) v1(169.747,186.003) v1(276.287,186.003) 362.182,186.003 362.302,185.884 383.226,185.884 383.431,186.089 386.24,186.089 CN25.102@386.365,186.215 ; v1(61.868,117.679) 61.868,116.421 62.375,115.913 U3.18@62.375,114.87 ; v1(275.999,16.994) 275.999,8.252 CN22.102@277.408,6.843
  Bottom Layer w0.203: v1(61.868,117.679) 63,118.811 63,185.576 v1(63.427,186.003) 64.427,187.003 64.427,232.738 64.646,232.957 64.646,235.794 CN23.102@64.52,235.92 ; v1(169.747,186.003) 170.747,187.003 170.747,232.738 170.966,232.957 170.966,235.794 CN21.102@170.84,235.92 ; v1(275.999,16.994) 275.999,17.179 275.531,17.647 275.531,37 275.531,185.247 v1(276.287,186.003) 277.287,187.003 277.287,232.738 277.506,232.957 277.506,235.794 CN24.102@277.38,235.92
H2-51: CN20.103 CN21.103 CN22.103 CN23.103 CN24.103 CN25.103 U2.16 U20.16 | length 800
  Top Layer w0.203: v1(17.192,189.937) 17.693,190.438 v1(59.393,190.438) v1(165.713,190.438) v1(272.253,190.438) 382.727,190.438 383.146,190.019 383.146,189.964 v1(383.174,189.992) ; v1(60.393,233.079) 60.393,236.873 CN23.103@61.98,238.46 ; v1(166.466,118.982) 166.604,118.982 167.675,117.911 167.675,113.744 169.419,112 176,112 177.675,113.675 U2.16@177.675,114.87 ; v1(166.713,233.079) 166.713,236.873 CN21.103@168.3,238.46 ; v1(273.253,233.079) 273.253,236.873 CN24.103@274.84,238.46
  Bottom Layer w0.203: CN20.103@11.46,188.7 12.697,189.937 v1(17.192,189.937) ; v1(59.393,190.438) 60.393,191.438 v1(60.393,233.079) ; v1(166.466,118.982) 165,120.448 165,189.726 v1(165.713,190.438) 166.713,191.438 v1(166.713,233.079) ; v1(273.253,233.079) 273.253,191.438 v1(272.253,190.438) 271.253,189.438 271.253,36 271.253,12.999 CN22.103@274.868,9.383 ; v1(383.174,189.992) 387.668,189.992 CN25.103@388.905,188.755
H2-52: CN20.104 CN21.104 CN22.104 CN23.104 CN24.104 CN25.104 U3.20 | length 774.2
  Top Layer w0.203: CN20.104@14,188.7 v1(60.879,188.7) v1(167.199,188.7) v1(273.739,188.7) 362.182,188.7 362.543,188.339 383.163,188.339 383.578,188.755 CN25.104@386.365,188.755 ; v1(60.568,117.679) 60.568,116.421 61.075,115.913 U3.20@61.075,114.87 ; v1(272,17) 272,10.795 274.868,7.927 CN22.104@274.868,6.843
  Bottom Layer w0.203: v1(60.568,117.679) 59.879,118.367 59.879,187.7 v1(60.879,188.7) 61.879,189.7 61.879,235.819 CN23.104@61.98,235.92 ; v1(167.199,188.7) 168.199,189.7 168.199,235.819 CN21.104@168.3,235.92 ; v1(272,17) 272.865,17.865 272.865,36 272.865,187.826 v1(273.739,188.7) 274.739,189.7 274.739,235.819 CN24.104@274.84,235.92
H2_N: CN20.54 CN21.54 CN22.54 CN24.54 CN25.54 S6.2A | length 837.5
  Top Layer w0.203: v1(22.007,124.924) 26,124.924 26.229,124.924 26.229,125.051 26.686,125.051 26.686,124.924 26.686,124.552 27.143,124.552 27.143,124.924 27.143,125.051 27.6,125.051 27.6,124.924 27.6,124.552 28.057,124.552 28.057,124.924 28.057,125.051 28.515,125.051 28.515,124.924 28.515,124.552 28.972,124.552 28.972,124.924 28.972,125.051 29.429,125.051 29.429,124.924 29.429,124.552 29.886,124.552 29.886,124.924 30,124.924 124.653,124.924 125.165,125.437 126.563,125.437 127,125 127.172,124.828 128.478,124.828 128.856,125.206 v1(135.855,125.206) v1(238.711,125.206) v1(349.711,125.206) v1(352.792,125.206) v1(376.984,125.206) ; v1(134.356,193) 134.356,196.431 134.475,196.55 S6.2A@135.27,196.55 ; CN21.54@231.8,235.92 231.8,229.119 231.681,229 229.439,229 229.32,228.881 229.32,227.591 229.407,227.503 230.91,226 234.295,226 238.711,221.583 v1(238.711,192) ; CN24.54@338.34,235.92 338.518,235.742 338.518,230.352 338.402,230.235 338.402,229.119 338.283,229 335.979,229 335.86,228.881 335.86,227.622 336.419,227.062 341.938,227.062 343,226 343.251,225.749 349.711,219.289 v1(349.711,192) ; CN22.54@338.368,6.843 338.349,6.824 337.314,6.824 336.184,5.695 336.184,5.526 337.048,4.662 338.633,4.662 339.792,3.503 339.87,3.425 345.425,3.425 348,6 348,8 345,11 342.289,13.711 342.289,45.705 338,49.994 338,104.006 351.882,117.888 v1(352.497,118.503)
  Bottom Layer w0.203: CN20.54@14,125.2 14.062,125.138 19,125.138 19.434,124.704 20.36,124.704 20.581,124.924 v1(22.007,124.924) ; v1(134.356,193) 134.356,126.706 v1(135.855,125.206) ; v1(238.711,125.206) v1(238.711,192) ; v1(349.711,125.206) v1(349.711,192) ; v1(352.497,118.503) 353.031,119.037 353.031,122.561 352.792,122.8 v1(352.792,125.206) ; v1(376.984,125.206) 376.996,125.193 386.304,125.193 CN25.54@386.365,125.255
H2_P: CN20.58 CN21.58 CN22.58 CN24.58 CN25.58 S6.1A | length 839.4
  Top Layer w0.203: v1(22.007,125.636) 124.358,125.636 124.825,126.102 126.903,126.102 127.503,125.503 128.147,125.503 128.561,125.917 v1(134.138,125.917) v1(238,125.917) v1(349,125.917) v1(353.503,125.917) v1(376.984,125.917) ; S6.1A@132.73,196.55 133.525,196.55 133.644,196.431 v1(133.644,193) ; CN21.58@226.72,235.92 226.72,233.004 226.775,232.949 226.775,232.507 226.658,232.391 226.658,229.119 226.777,229 228.489,229 228.608,228.881 228.608,227.296 228.904,227 230.616,225.289 234,225.289 238,221.289 v1(238,192) ; CN24.58@333.26,235.92 333.26,233.004 333.315,232.949 333.315,232.507 333.198,232.391 333.198,229.119 333.317,229 335.029,229 335.148,228.881 335.148,227.296 336.093,226.351 341.643,226.351 349,218.994 v1(349,192) ; CN22.58@333.288,6.843 333.307,6.824 334.343,6.824 335.473,5.695 335.473,5.232 336.754,3.951 338.338,3.951 339.575,2.713 345.719,2.713 348.711,5.705 348.711,8.295 345,12.006 343,14.006 343,46 338.711,50.289 338.711,103.711 352.594,117.594 v1(353,118)
  Bottom Layer w0.203: CN20.58@14,130.28 14.062,130.342 19,130.342 19.61,129.732 19.61,125.534 19.729,125.415 20.066,125.415 20.286,125.636 v1(22.007,125.636) ; v1(133.644,193) 133.644,126.411 v1(134.138,125.917) ; v1(238,125.917) v1(238,192) ; v1(349,125.917) v1(349,192) ; v1(353,118) 353.742,118.742 353.742,122.856 353.503,123.095 v1(353.503,125.917) ; v1(376.984,125.917) 379.021,127.955 379.021,128.418 381,130.396 382.836,130.396 382.953,130.28 383.395,130.28 383.45,130.335 CN25.58@386.365,130.335
MISO_CHN_1: SOM1.JX1-31 U8.9 | length 92.8
  Top Layer w0.203: U8.9@76.275,109.13 76.275,108.087 76.782,107.579 v1(76.782,106.321) ; v1(76.782,88.57) 81.546,88.57 81.795,88.321 96.639,88.321 100.237,91.92 106.983,91.92 110.155,88.748 138.9,88.748 142.991,84.657 143,84.657 SOM1.JX1-31@143,83.45
  Bottom Layer w0.203: v1(76.782,88.57) v1(76.782,106.321)
MISO_CHN_2: SOM1.JX1-83 U11.9 | length 77.5
  Top Layer w0.203: SOM1.JX1-83@163.8,83.45 163.8,84.568 164.052,84.568 164.23,84.746 167.37,84.746 167.4,84.715 167.43,84.746 168.17,84.746 168.2,84.715 168.23,84.746 169.77,84.746 169.8,84.715 169.83,84.746 192.703,84.746 195.875,87.918 199.305,87.918 203.604,83.619 210.834,83.619 v1(211.782,84.568) ; U11.9@211.275,109.13 211.275,108.087 211.782,107.579 v1(211.782,106.321)
  Bottom Layer w0.279: v1(211.782,84.568) v1(211.782,106.321)
MISO_CHN_3: SOM1.JX2-53 U17.3 | length 124.7
  Top Layer w0.203: SOM1.JX2-53@151.8,39 151.8,40.207 151.809,40.207 158.136,46.534 v1(244.868,46.534) ; v1(244.868,71.321) 244.868,72.579 245.375,73.087 U17.3@245.375,74.13
  Bottom Layer w0.279: v1(244.868,46.534) v1(244.868,71.321)
MISO_SENSORS: U17.18 U21.40 | length 23.1
  Top Layer w0.203: U17.18@245.375,79.87 245.375,80.913 244.868,81.421 244.868,82.868 246.369,84.369 v1(256,84.369) v1@256.032,84.369 ; v1(256,89) 257.75,90.75 U21.40@257.75,91.75
  Bottom Layer w0.203: v1(256,84.369) v1(256,89)
MOSI_CHN_1: SOM1.JX1-25 U8.5 | length 94
  Top Layer w0.203: v1(73.675,87.452) 75.161,87.452 75.416,87.197 97.096,87.197 100.7,90.802 106.52,90.802 109.692,87.63 137.618,87.63 140.591,84.657 140.6,84.657 SOM1.JX1-25@140.6,83.45 ; v1(73.675,106.321) U8.5@73.675,109.13
  Bottom Layer w0.203: v1(73.675,87.452) v1(73.675,106.321)
MOSI_CHN_2: SOM1.JX2-20 U14.4 | length 176.3
  Top Layer w0.203: SOM1.JX2-20@138.2,34.6 138.2,33.394 138.415,33.394 150.891,20.917 186.873,20.917 190.089,17.702 204.513,17.702 208.513,21.702 v1(217.518,21.702) ; v1(217.518,107.006) 217.518,107.579 218.025,108.087 U14.4@218.025,109.13
  Bottom Layer w0.279: v1(217.518,21.702) v1(217.518,107.006)
MOSI_CHN_3: SOM1.JX2-56 U17.4 | length 145.4
  Top Layer w0.203: SOM1.JX2-56@152.6,34.6 152.6,33.394 152.815,33.394 158.583,27.625 189.652,27.625 192.867,24.41 201.734,24.41 205.734,28.41 v1(245.518,28.41) ; v1(245.518,72.006) 245.518,72.579 246.025,73.087 U17.4@246.025,74.13
  Bottom Layer w0.279: v1(245.518,28.41) v1(245.518,72.006)
MOSI_SENSORS: U17.17 U21.39 | length 22.3
  Top Layer w0.203: U17.17@246.025,79.87 246.025,80.913 245.518,81.421 245.518,82.978 246.292,83.753 v1(255,83.753) ; v1(255,89) 255.576,89.576 255.961,89.576 257.202,90.817 257.202,91.702 U21.39@257.25,91.75
  Bottom Layer w0.203: v1(255,83.753) v1(255,89)
NC_KILL_SWITCH_1: CN4.1 CN4.2 S1.1 | length 9.6
  Top Layer w0.203: S1.1@12.245,53.8 17.59,53.8 19.374,52.016 CN4.1@19.774,52.016 CN4.2@19.774,53.266 CN4.2@19.75,53.241
NC_KILL_SWITCH_2: CN5.1 CN5.2 S7.1 | length 9.3
  Top Layer w0.203: S7.1@12.239,68 18.264,68 19.38,69.116 CN5.1@19.78,69.116 CN5.2@19.78,70.366
NetC3_2: C3.2 J1.1 R1.1 | length 18.7
  Top Layer w0.203: R1.1@70.016,19 74.46,19 J1.1@78.46,15 78.46,21.39 76.925,22.925 C3.2@76.925,23
NetC8_2: C8.2 J1.2 J1.4 J1.6 R6.2 U25.3 | length 47.6
  Top Layer w0.203: U25.3@54.512,11.185 54.512,11.019 54.702,10.829 55.171,10.829 v1(56,10) ; v1(75,11) 79.92,11 J1.6@81,9.92 ; J1.2@81,15 J1.4@81,12.46 J1.6@81,9.92 ; C8.2@91.691,4.625 90.466,4.625 89.857,4.016 R6.2@87,4.016 87,6 83.08,9.92 J1.6@81,9.92
  Bottom Layer w0.203: v1(56,10) 66,10 67,11 v1(75,11)
NetC10_1: C10.1 R9.1 R11.1 U27.3 | length 16.9
  Top Layer w0.203: R9.1@55.843,33.578 55.843,34.843 56,35 56,37.984 R11.1@56.016,38 56.016,37.838 56.514,37.34 56.676,37.34 57.016,37 59.695,37 U27.3@59.745,37.05 59.745,35.255 62,33 C10.1@62,29.85
NetC14_1: C14.1 U21.13 U21.14 | length 8.3
  Top Layer w0.203: U21.14@261.25,100.25 U21.13@261.75,100.25 267.6,100.25 268.925,98.925 C14.1@269,98.925
NetC15_1: C15.1 U21.11 | length 3
  Top Layer w0.203: U21.11@263.25,98.25 265.25,98.25 265.925,98.925 C15.1@266,98.925
NetC16_1: C16.1 U21.48 | length 12.5
  Top Layer w0.203: U21.48@261.75,91.75 261.75,82.4 263.6,80.55 C16.1@263.6,80
NetC16_2: C16.2 U21.47 | length 12.1
  Top Layer w0.203: C16.2@260.4,80 260.4,80.55 261.25,81.4 U21.47@261.25,91.75
NetC17_1: C17.1 U21.46 | length 9.1
  Top Layer w0.203: U21.46@260.75,91.75 260.798,91.798 260.798,92.679 261.119,93 262.05,93 266.45,88.6 C17.1@267,88.6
